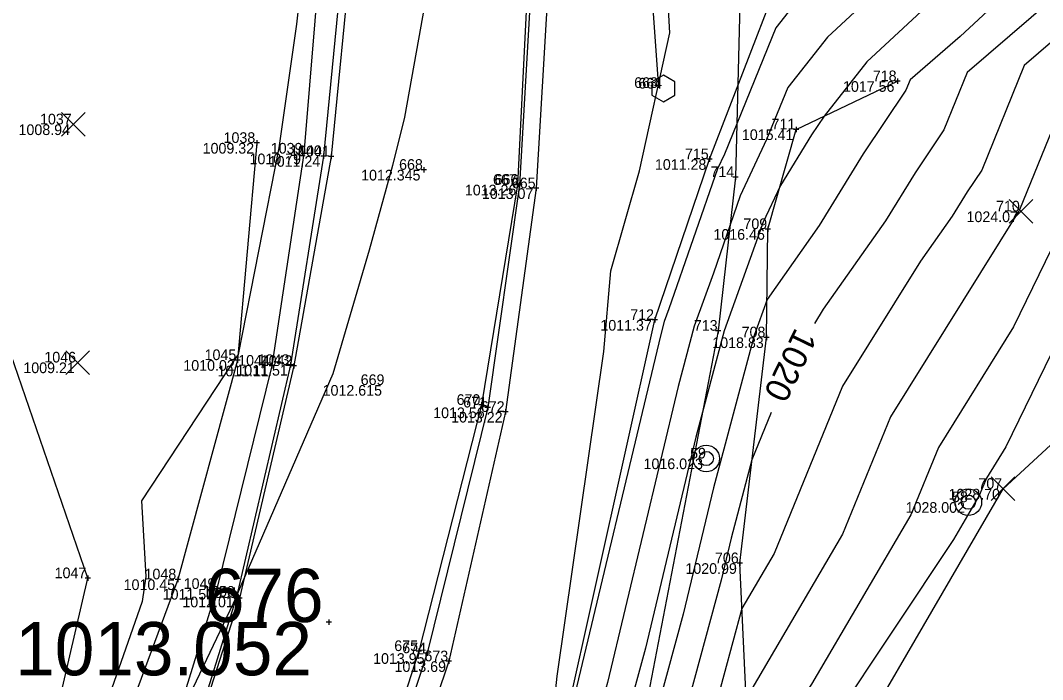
# Model space of a CAD drawing. Extents: x 2354693 to 2355622, y 637071 to 710080.
# Drawn here: x 2355315.1 to 2355430.4, y 709108.7 to 709182.9 of the extents above; entities that cross this region are included whole.
import ezdxf

# ---------------------------------------------------------------- set-up
doc = ezdxf.new("R2010")
doc.units = 0
for name, color, linetype in [('Default', 7, 'Continuous'), ('DT_X_Contour_Major', 7, 'Continuous'), ('DT_X_Contour_Minor', 7, 'Continuous'), ('PM_X_Surveyed_Line', 7, 'Continuous'), ('PV_X_EOP', 7, 'Continuous'), ('PV_X_Shoulder', 7, 'Continuous'), ('RD_X_Cells', 7, 'Continuous'), ('RD_X_GR_Lt', 7, 'Continuous'), ('SV_X_Mon_Cells_Found', 7, 'Continuous'), ('SV_X_Random_Point', 7, 'Continuous'), ('SV_X_Shot_Marker', 7, 'Continuous'), ('SV_X_Text_Elevation', 7, 'Continuous'), ('SV_X_Text_Name', 7, 'Continuous'), ('SV_X_Toe_of_Slope', 7, 'Continuous'), ('SV_X_Top_of_Bank', 7, 'Continuous'), ('VG_X_Tree_Line_Rt', 7, 'Continuous')]:
    doc.layers.add(name, color=color, linetype=linetype)

msp = doc.modelspace()

# ---------------------------------------------------------------- linework, layer by layer
at = {"layer": 'Default'}
msp.add_lwpolyline([(2355263.76, 708986.4), (2355330.91, 709003.61), (2355347.35, 709002.09), (2355387.45, 709051.54), (2355402.1, 709089.16), (2355425.96, 709130.16), (2355495.56, 709194.41), (2355530.33, 709221.46), (2355525, 709302.12), (2355509.66, 709318.33), (2355534.8, 709413.26), (2355566.11, 709428.47), (2355585.74, 709473.78), (2355589.64, 709532.44), (2355608.23, 709591.27)], dxfattribs=at)
msp.add_lwpolyline([(2355263.76, 708986.4), (2355330.91, 709003.61), (2355347.35, 709002.09), (2355387.45, 709051.54), (2355402.1, 709089.16), (2355425.96, 709130.16), (2355495.56, 709194.41), (2355530.33, 709221.46), (2355525, 709302.12), (2355509.66, 709318.33), (2355534.8, 709413.26), (2355566.11, 709428.47), (2355585.74, 709473.78), (2355589.64, 709532.44), (2355608.23, 709591.27)], dxfattribs=at)
at = {"layer": 'DT_X_Contour_Major'}
for points in [[(2355456.69, 709227.11), (2355457.48, 709226.2), (2355459.26, 709225.12), (2355454.22, 709205.33), (2355454.08, 709205.14), (2355453.9, 709204.8), (2355453.96, 709204.72), (2355452.92, 709203.76), (2355421.91, 709177.07), (2355419.27, 709170.6), (2355416.05, 709165.77), (2355412.7, 709160.36), (2355405.68, 709150.4), (2355404.68, 709148.79)], [(2355456.69, 709227.11), (2355457.48, 709226.2), (2355459.26, 709225.12), (2355454.22, 709205.33), (2355454.08, 709205.14), (2355453.9, 709204.8), (2355453.96, 709204.72), (2355452.92, 709203.76), (2355421.91, 709177.07), (2355419.27, 709170.6), (2355416.05, 709165.77), (2355412.7, 709160.36), (2355405.68, 709150.4), (2355404.68, 709148.79)], [(2355347.04, 709193.49), (2355347.17, 709190.66), (2355346.28, 709182.54), (2355344.27, 709168.58), (2355339.69, 709145.3), (2355339.23, 709144.66), (2355328.8, 709128.82), (2355329.27, 709120.28), (2355328.85, 709117.46), (2355322.25, 709098.57)], [(2355347.04, 709193.49), (2355347.17, 709190.66), (2355346.28, 709182.54), (2355344.27, 709168.58), (2355339.69, 709145.3), (2355339.23, 709144.66), (2355328.8, 709128.82), (2355329.27, 709120.28), (2355328.85, 709117.46), (2355322.25, 709098.57)], [(2355399.81, 709138.75), (2355397.63, 709133.42), (2355395.27, 709124.59), (2355394.15, 709119.88), (2355389.34, 709102.14), (2355388.09, 709097.39), (2355383.82, 709092.9), (2355374.92, 709068.12), (2355369.01, 709054.1), (2355364.95, 709045.81)], [(2355399.81, 709138.75), (2355397.63, 709133.42), (2355395.27, 709124.59), (2355394.15, 709119.88), (2355389.34, 709102.14), (2355388.09, 709097.39), (2355383.82, 709092.9), (2355374.92, 709068.12), (2355369.01, 709054.1), (2355364.95, 709045.81)]]:
    msp.add_lwpolyline(points, dxfattribs=at)
at = {"layer": 'DT_X_Contour_Minor'}
for points in [[(2355432.86, 709227.06), (2355429.2, 709222.75), (2355423.82, 709215.5), (2355413.6, 709196.23), (2355417.38, 709191.51), (2355406.15, 709181.07), (2355401.67, 709175.4), (2355399.28, 709169.52), (2355396.31, 709163.17), (2355393.28, 709154.48), (2355391.12, 709148.5), (2355389.3, 709141.69), (2355381.34, 709108.35), (2355380.04, 709103.59), (2355379.71, 709102.31), (2355378.56, 709101.1), (2355376.17, 709094.45), (2355359.35, 709054.56), (2355355.96, 709047.61), (2355331.07, 709003.59)], [(2355432.86, 709227.06), (2355429.2, 709222.75), (2355423.82, 709215.5), (2355413.6, 709196.23), (2355417.38, 709191.51), (2355406.15, 709181.07), (2355401.67, 709175.4), (2355399.28, 709169.52), (2355396.31, 709163.17), (2355393.28, 709154.48), (2355391.12, 709148.5), (2355389.3, 709141.69), (2355381.34, 709108.35), (2355380.04, 709103.59), (2355379.71, 709102.31), (2355378.56, 709101.1), (2355376.17, 709094.45), (2355359.35, 709054.56), (2355355.96, 709047.61), (2355331.07, 709003.59)], [(2355433.91, 709212.05), (2355427.03, 709199.09), (2355429.57, 709195.91), (2355410.59, 709178.28), (2355405.76, 709172.16), (2355404.34, 709170.04), (2355400.84, 709164.36), (2355398.86, 709160.13), (2355398.29, 709158.51), (2355394.5, 709147.97), (2355391.29, 709135.99), (2355385.61, 709112.19), (2355383.14, 709103.1), (2355382.5, 709100.67), (2355380.31, 709098.37), (2355375.75, 709085.67), (2355362.57, 709054.41), (2355353.88, 709036.62), (2355335, 709003.23)], [(2355433.91, 709212.05), (2355427.03, 709199.09), (2355429.57, 709195.91), (2355410.59, 709178.28), (2355405.76, 709172.16), (2355404.34, 709170.04), (2355400.84, 709164.36), (2355398.86, 709160.13), (2355398.29, 709158.51), (2355394.5, 709147.97), (2355391.29, 709135.99), (2355385.61, 709112.19), (2355383.14, 709103.1), (2355382.5, 709100.67), (2355380.31, 709098.37), (2355375.75, 709085.67), (2355362.57, 709054.41), (2355353.88, 709036.62), (2355335, 709003.23)], [(2355455.82, 709201.52), (2355428.34, 709177.87), (2355423.54, 709166.09), (2355421.9, 709163.64), (2355420.2, 709160.88), (2355416.62, 709155.81), (2355407.85, 709141.74), (2355400.15, 709122.88), (2355396.5, 709116.66), (2355392.43, 709101.65), (2355390.88, 709095.75), (2355385.57, 709090.16), (2355374.5, 709059.34), (2355372.23, 709053.95), (2355347.65, 709003.65), (2355346.79, 709002.14)], [(2355455.82, 709201.52), (2355428.34, 709177.87), (2355423.54, 709166.09), (2355421.9, 709163.64), (2355420.2, 709160.88), (2355416.62, 709155.81), (2355407.85, 709141.74), (2355400.15, 709122.88), (2355396.5, 709116.66), (2355392.43, 709101.65), (2355390.88, 709095.75), (2355385.57, 709090.16), (2355374.5, 709059.34), (2355372.23, 709053.95), (2355347.65, 709003.65), (2355346.79, 709002.14)], [(2355401.7, 709183.87), (2355400.31, 709182.11), (2355394.55, 709167.89), (2355393.76, 709166.21), (2355388.26, 709150.46), (2355387.74, 709149.02), (2355387.31, 709147.39), (2355377.07, 709104.51), (2355376.95, 709104.07), (2355376.92, 709103.95), (2355376.81, 709103.84), (2355376.59, 709103.23), (2355372.38, 709093.25), (2355374.65, 709102.38), (2355375.23, 709104.82), (2355375.66, 709109.07), (2355380.92, 709145.65), (2355381.7, 709154.71), (2355384.94, 709165.98), (2355388.38, 709181.55), (2355387.25, 709201.61)], [(2355401.7, 709183.87), (2355400.31, 709182.11), (2355394.55, 709167.89), (2355393.76, 709166.21), (2355388.26, 709150.46), (2355387.74, 709149.02), (2355387.31, 709147.39), (2355377.07, 709104.51), (2355376.95, 709104.07), (2355376.92, 709103.95), (2355376.81, 709103.84), (2355376.59, 709103.23), (2355372.38, 709093.25), (2355374.65, 709102.38), (2355375.23, 709104.82), (2355375.66, 709109.07), (2355380.92, 709145.65), (2355381.7, 709154.71), (2355384.94, 709165.98), (2355388.38, 709181.55), (2355387.25, 709201.61)], [(2355441.77, 709200.32), (2355421.1, 709181.12), (2355415.48, 709176.27), (2355415, 709175.1), (2355410.19, 709167.9), (2355405.21, 709159.83), (2355399.33, 709151.49), (2355397.87, 709147.45), (2355393.28, 709130.29), (2355389.88, 709116.04), (2355386.24, 709102.62), (2355385.3, 709099.03), (2355382.07, 709095.63), (2355375.33, 709076.89), (2355365.79, 709054.26), (2355351.8, 709025.63), (2355338.93, 709002.87)], [(2355441.77, 709200.32), (2355421.1, 709181.12), (2355415.48, 709176.27), (2355415, 709175.1), (2355410.19, 709167.9), (2355405.21, 709159.83), (2355399.33, 709151.49), (2355397.87, 709147.45), (2355393.28, 709130.29), (2355389.88, 709116.04), (2355386.24, 709102.62), (2355385.3, 709099.03), (2355382.07, 709095.63), (2355375.33, 709076.89), (2355365.79, 709054.26), (2355351.8, 709025.63), (2355338.93, 709002.87)], [(2355362.05, 709192.16), (2355358.45, 709172.04), (2355357.11, 709166.59), (2355354.46, 709157.07), (2355350.37, 709143.12), (2355339.59, 709118.3), (2355339.54, 709118.17), (2355339.49, 709118.02), (2355332.34, 709102.98), (2355330.16, 709098.09), (2355328.96, 709094.77), (2355325.41, 709087), (2355319.12, 709073.27), (2355312.74, 709068.84), (2355306.43, 709059.31), (2355290.09, 709038.24), (2355286.78, 709031.66), (2355285.96, 709030.24), (2355285.39, 709028.91), (2355262.53, 708987.18)], [(2355362.05, 709192.16), (2355358.45, 709172.04), (2355357.11, 709166.59), (2355354.46, 709157.07), (2355350.37, 709143.12), (2355339.59, 709118.3), (2355339.54, 709118.17), (2355339.49, 709118.02), (2355332.34, 709102.98), (2355330.16, 709098.09), (2355328.96, 709094.77), (2355325.41, 709087), (2355319.12, 709073.27), (2355312.74, 709068.84), (2355306.43, 709059.31), (2355290.09, 709038.24), (2355286.78, 709031.66), (2355285.96, 709030.24), (2355285.39, 709028.91), (2355262.53, 708987.18)], [(2355434.77, 709178.67), (2355427.81, 709161.59), (2355427.75, 709161.5), (2355427.69, 709161.4), (2355427.56, 709161.22), (2355413.25, 709138.29), (2355407.86, 709125.05), (2355396.98, 709106.54), (2355395.53, 709101.17), (2355393.68, 709094.11), (2355387.32, 709087.42), (2355375.84, 709055.46), (2355374.95, 709053.73), (2355351.99, 709007.81)], [(2355434.77, 709178.67), (2355427.81, 709161.59), (2355427.75, 709161.5), (2355427.69, 709161.4), (2355427.56, 709161.22), (2355413.25, 709138.29), (2355407.86, 709125.05), (2355396.98, 709106.54), (2355395.53, 709101.17), (2355393.68, 709094.11), (2355387.32, 709087.42), (2355375.84, 709055.46), (2355374.95, 709053.73), (2355351.99, 709007.81)], [(2355443.81, 709170.88), (2355426.26, 709134.89), (2355424.07, 709131.37), (2355423.26, 709129.4), (2355420.36, 709124.46), (2355400.1, 709094.01), (2355399.26, 709090.83), (2355390.83, 709081.95), (2355384.38, 709064), (2355378.76, 709053.06), (2355362.8, 709021.14)], [(2355443.81, 709170.88), (2355426.26, 709134.89), (2355424.07, 709131.37), (2355423.26, 709129.4), (2355420.36, 709124.46), (2355400.1, 709094.01), (2355399.26, 709090.83), (2355390.83, 709081.95), (2355384.38, 709064), (2355378.76, 709053.06), (2355362.8, 709021.14)], [(2355435.74, 709166.06), (2355427.13, 709148.41), (2355418.66, 709134.83), (2355415.56, 709127.23), (2355404.35, 709108.14), (2355398.13, 709098.79), (2355396.47, 709092.47), (2355389.07, 709084.69), (2355380.11, 709059.73), (2355376.86, 709053.4), (2355357.39, 709014.47)], [(2355435.74, 709166.06), (2355427.13, 709148.41), (2355418.66, 709134.83), (2355415.56, 709127.23), (2355404.35, 709108.14), (2355398.13, 709098.79), (2355396.47, 709092.47), (2355389.07, 709084.69), (2355380.11, 709059.73), (2355376.86, 709053.4), (2355357.39, 709014.47)]]:
    msp.add_lwpolyline(points, dxfattribs=at)
at = {"layer": 'PM_X_Surveyed_Line'}
for points in [[(2355180.15, 709561.24), (2355214.75, 709522.89), (2355249.31, 709484.27), (2355284.02, 709443.14), (2355315.55, 709399.77), (2355328.89, 709377.57), (2355342.97, 709349.79), (2355353.37, 709324.19), (2355361.35, 709299.65), (2355367.76, 709272.47), (2355372.19, 709243.49), (2355373.87, 709217.88), (2355371.21, 709164.41), (2355367.13, 709139.62), (2355360.06, 709111.88), (2355351.62, 709085.78), (2355342.5, 709062.34), (2355329.45, 709031.42), (2355320.62, 709012.58)], [(2355165.86, 709547.27), (2355199.55, 709510.04), (2355233.99, 709470.59), (2355267.54, 709430.37), (2355282.6, 709410.56), (2355297.68, 709388.57), (2355309.4, 709369.45), (2355323.83, 709342.43), (2355334.06, 709318.38), (2355342.29, 709293.43), (2355348.47, 709267.17), (2355351.87, 709240.38), (2355352.96, 709217.38), (2355352.46, 709191.09), (2355350.19, 709167.62), (2355345.96, 709144.01), (2355339.85, 709117.86), (2355332.1, 709093.74), (2355322.6, 709069.08), (2355314.61, 709050.66), (2355300.36, 709021.7)]]:
    msp.add_lwpolyline(points, dxfattribs=at)
at = {"layer": 'PV_X_EOP'}
for points in [[(2355180.81, 709561.74), (2355215.64, 709523.56), (2355249.92, 709484.36), (2355284.41, 709443.36), (2355315.94, 709399.97), (2355329.75, 709378.36), (2355343.52, 709350.1), (2355349.22, 709351.4), (2355359.3, 709326.8), (2355367.59, 709301.75), (2355374.11, 709275.91), (2355368.17, 709272.69), (2355372.5, 709243.56), (2355374.5, 709217.66), (2355371.41, 709164.43), (2355367.84, 709139.33), (2355361.02, 709111.64), (2355352.39, 709085.56), (2355343.44, 709061.97), (2355330.49, 709031.08), (2355321.14, 709011.8)], [(2355165.32, 709546.95), (2355198.99, 709509.5), (2355233.4, 709470.11), (2355266.73, 709429.76), (2355281.93, 709410.08), (2355297.05, 709388.17), (2355308.64, 709369.04), (2355321.45, 709342.93), (2355321.34, 709342.62), (2355331.82, 709317.68), (2355340.04, 709292.97), (2355346.6, 709266.72), (2355349.96, 709239.9), (2355351.76, 709217.38), (2355351.56, 709190.76), (2355349.32, 709167.66), (2355345.61, 709144.12), (2355339.52, 709118.01), (2355331.95, 709093.67), (2355322.31, 709069.24), (2355314.27, 709051.11), (2355300.29, 709022.25)]]:
    msp.add_lwpolyline(points, dxfattribs=at)
at = {"layer": 'PV_X_Shoulder'}
for points in [[(2355370.56, 709271.65), (2355375.13, 709244.15), (2355376.46, 709217.44), (2355373.31, 709164.03), (2355369.83, 709138.83), (2355363.46, 709110.73), (2355354.73, 709084.84), (2355345.67, 709061.24), (2355332.68, 709029.85), (2355323.4, 709011.31)], [(2355350.69, 709226.18), (2355349.24, 709225.72), (2355348.98, 709190.63), (2355347.11, 709167.94), (2355343.48, 709144.04), (2355337.29, 709118.88), (2355329.72, 709094.53), (2355320.78, 709071.24), (2355312.54, 709052.23), (2355299, 709024.07)]]:
    msp.add_lwpolyline(points, dxfattribs=at)
at = {"layer": 'RD_X_Cells'}
msp.add_lwpolyline([(2355386.34, 709174.52), (2355387.64, 709173.77), (2355388.94, 709174.52), (2355388.94, 709176.02), (2355387.64, 709176.77), (2355386.34, 709176.02), (2355386.34, 709174.52)], dxfattribs=at)
at = {"layer": 'RD_X_GR_Lt'}
msp.add_lwpolyline([(2355373.99, 709277.32), (2355381.03, 709242.7), (2355383.59, 709226.42), (2355385.2, 709201.58), (2355387.11, 709175.34)], dxfattribs=at)
at = {"layer": 'SV_X_Mon_Cells_Found'}
for centre, radius in [((2355392.48, 709133.58), 1.5), ((2355392.48, 709133.58), 0.8), ((2355422.03, 709128.66), 1.5), ((2355422.03, 709128.66), 0.8)]:
    msp.add_circle(centre, radius, dxfattribs=at)
at = {"layer": 'SV_X_Random_Point'}
for p, q in [((2355319.77, 709169.89), (2355322.43, 709172.56)), ((2355319.77, 709172.56), (2355322.43, 709169.89)), ((2355426.63, 709160.09), (2355429.3, 709162.76)), ((2355426.63, 709162.76), (2355429.3, 709160.09)), ((2355320.26, 709143.06), (2355322.93, 709145.73)), ((2355320.26, 709145.73), (2355322.93, 709143.06)), ((2355424.62, 709128.83), (2355427.29, 709131.5)), ((2355424.62, 709131.5), (2355427.29, 709128.83))]:
    msp.add_line(p, q, dxfattribs=at)
at = {"layer": 'SV_X_Shot_Marker'}
for p, q in [((2355414.35, 709176.1), (2355413.75, 709176.1)), ((2355414.05, 709176.4), (2355414.05, 709175.8)), ((2355402.62, 709170.97), (2355402.62, 709170.37)), ((2355402.92, 709170.67), (2355402.32, 709170.67)), ((2355342.11, 709169.14), (2355341.51, 709169.14)), ((2355341.81, 709169.44), (2355341.81, 709168.84)), ((2355347.41, 709167.94), (2355346.81, 709167.94)), ((2355347.11, 709168.24), (2355347.11, 709167.64)), ((2355349.62, 709167.66), (2355349.02, 709167.66)), ((2355349.32, 709167.96), (2355349.32, 709167.36)), ((2355350.49, 709167.62), (2355349.89, 709167.62)), ((2355350.19, 709167.92), (2355350.19, 709167.32)), ((2355392.84, 709167.61), (2355392.84, 709167.01)), ((2355360.63, 709166.41), (2355360.63, 709165.81)), ((2355393.14, 709167.31), (2355392.54, 709167.31)), ((2355360.93, 709166.11), (2355360.33, 709166.11)), ((2355396.06, 709165.3), (2355395.46, 709165.3)), ((2355395.76, 709165.6), (2355395.76, 709165)), ((2355371.51, 709164.41), (2355370.91, 709164.41)), ((2355371.71, 709164.43), (2355371.11, 709164.43)), ((2355371.21, 709164.71), (2355371.21, 709164.11)), ((2355371.41, 709164.73), (2355371.41, 709164.13)), ((2355373.61, 709164.03), (2355373.01, 709164.03)), ((2355373.31, 709164.33), (2355373.31, 709163.73)), ((2355399.74, 709159.43), (2355399.14, 709159.43)), ((2355399.44, 709159.73), (2355399.44, 709159.13)), ((2355386.98, 709149.19), (2355386.38, 709149.19)), ((2355386.68, 709149.49), (2355386.68, 709148.89)), ((2355394.13, 709147.98), (2355393.53, 709147.98)), ((2355393.83, 709148.28), (2355393.83, 709147.68)), ((2355399.57, 709147.23), (2355398.97, 709147.23)), ((2355399.27, 709147.53), (2355399.27, 709146.93)), ((2355339.93, 709144.67), (2355339.33, 709144.67)), ((2355339.63, 709144.97), (2355339.63, 709144.37)), ((2355343.48, 709144.34), (2355343.48, 709143.74)), ((2355345.61, 709144.42), (2355345.61, 709143.82)), ((2355343.78, 709144.04), (2355343.18, 709144.04)), ((2355345.91, 709144.12), (2355345.31, 709144.12)), ((2355346.26, 709144.01), (2355345.66, 709144.01)), ((2355345.96, 709144.31), (2355345.96, 709143.71)), ((2355367.13, 709139.93), (2355367.13, 709139.32)), ((2355367.43, 709139.62), (2355366.83, 709139.62)), ((2355368.14, 709139.33), (2355367.54, 709139.33)), ((2355367.84, 709139.63), (2355367.84, 709139.03)), ((2355370.13, 709138.83), (2355369.53, 709138.83)), ((2355369.83, 709139.13), (2355369.83, 709138.53)), ((2355396.56, 709121.78), (2355395.96, 709121.78)), ((2355396.26, 709122.08), (2355396.26, 709121.48)), ((2355322.75, 709120.39), (2355322.75, 709119.79)), ((2355332.89, 709120.26), (2355332.89, 709119.66)), ((2355323.05, 709120.09), (2355322.45, 709120.09)), ((2355333.19, 709119.96), (2355332.59, 709119.96)), ((2355337.29, 709119.18), (2355337.29, 709118.58)), ((2355337.59, 709118.88), (2355336.99, 709118.88)), ((2355339.82, 709118.01), (2355339.22, 709118.01)), ((2355339.52, 709118.31), (2355339.52, 709117.71)), ((2355340.15, 709117.86), (2355339.55, 709117.86)), ((2355339.85, 709118.16), (2355339.85, 709117.56)), ((2355350.23, 709115.15), (2355349.63, 709115.15)), ((2355349.93, 709115.45), (2355349.93, 709114.85)), ((2355360.06, 709112.18), (2355360.06, 709111.58)), ((2355360.36, 709111.88), (2355359.76, 709111.88)), ((2355361.32, 709111.64), (2355360.72, 709111.64)), ((2355361.02, 709111.94), (2355361.02, 709111.34)), ((2355363.46, 709111.03), (2355363.46, 709110.43)), ((2355363.76, 709110.73), (2355363.16, 709110.73))]:
    msp.add_line(p, q, dxfattribs=at)
at = {"layer": 'SV_X_Toe_of_Slope'}
for points in [[(2355330.91, 709003.61), (2355357.29, 709054.66), (2355376.63, 709104.12), (2355386.68, 709149.19), (2355392.84, 709167.31), (2355399.71, 709185.13), (2355454.61, 709204.96), (2355491.09, 709216.85), (2355522.63, 709235.09)], [(2355341.81, 709169.14), (2355339.63, 709144.67), (2355332.89, 709119.96), (2355324.12, 709096.3), (2355318.2, 709074.39)]]:
    msp.add_lwpolyline(points, dxfattribs=at)
at = {"layer": 'SV_X_Top_of_Bank'}
msp.add_lwpolyline([(2355387.45, 709051.54), (2355395.31, 709074.94), (2355402.1, 709089.16), (2355397.25, 709100.9), (2355396.26, 709121.78), (2355399.27, 709147.23), (2355399.44, 709159.43), (2355402.62, 709170.67), (2355414.05, 709176.1)], dxfattribs=at)
at = {"layer": 'VG_X_Tree_Line_Rt'}
for points in [[(2355286.87, 709031.33), (2355312.43, 709075.83), (2355322.75, 709120.09), (2355304.91, 709171.78), (2355297.85, 709210.36), (2355206.48, 709334.22), (2355207.86, 709373.6), (2355249.36, 709399.77), (2355239.7, 709433.16), (2355219.43, 709459.42), (2355185.29, 709497.16), (2355152.29, 709534.91)], [(2355430.11, 709344.44), (2355398.4, 709251.33), (2355397.95, 709252.38), (2355395.76, 709165.3), (2355393.83, 709147.98), (2355384.97, 709102.06), (2355364.4, 709052.05), (2355337.3, 709001.3)]]:
    msp.add_lwpolyline(points, dxfattribs=at)

# ---------------------------------------------------------------- texts
at = {"layer": 'DT_X_Contour_Major'}
msp.add_text('1020', height=2.8, rotation=244.1244, dxfattribs=at).set_placement((2355402.54, 709148.42))
msp.add_text('1020', height=2.8, rotation=244.1244, dxfattribs=at).set_placement((2355402.54, 709148.42))
at = {"layer": 'SV_X_Text_Elevation'}
for s, height, p in [('1017.56', 1.2, (2355407.9, 709174.9)), ('1008.94', 1.2, (2355314.93, 709170.03)), ('1015.41', 1.2, (2355396.5, 709169.47)), ('1009.32', 1.2, (2355335.69, 709167.94)), ('1010.79', 1.2, (2355340.98, 709166.74)), ('1011.24', 1.2, (2355343.15, 709166.46)), ('1011.28', 1.2, (2355386.69, 709166.11)), ('1012.345', 1.2, (2355353.56, 709164.91)), ('1013.26', 1.2, (2355365.26, 709163.23)), ('1013.07', 1.2, (2355367.18, 709162.83)), ('1024.07', 1.2, (2355421.83, 709160.22)), ('1016.46', 1.2, (2355393.29, 709158.23)), ('1011.37', 1.2, (2355380.54, 709147.99)), ('1018.83', 1.2, (2355393.16, 709146.03)), ('1009.21', 1.2, (2355315.47, 709143.2)), ('1010.02', 1.2, (2355333.51, 709143.47)), ('1011.11', 1.2, (2355337.36, 709142.84)), ('1011.51', 1.2, (2355339.49, 709142.92)), ('1012.615', 1.2, (2355349.22, 709140.66)), ('1013.56', 1.2, (2355361.69, 709138.13)), ('1013.22', 1.2, (2355363.71, 709137.63)), ('1016.023', 1.2, (2355385.41, 709132.38)), ('1028.70', 1.2, (2355419.8, 709128.96)), ('1028.002', 1.2, (2355414.96, 709127.46)), ('1020.99', 1.2, (2355390.13, 709120.58)), ('1010.45', 1.2, (2355326.78, 709118.76)), ('1011.53', 1.2, (2355331.18, 709117.68)), ('1012.01', 1.2, (2355333.4, 709116.81)), ('1013.052', 6, (2355314.55, 709109.15)), ('1013.95', 1.2, (2355354.91, 709110.44)), ('1013.69', 1.2, (2355357.33, 709109.53))]:
    msp.add_text(s, height=height, dxfattribs=at).set_placement(p)
at = {"layer": 'SV_X_Text_Name'}
for s, height, p in [('718', 1.2, (2355411.26, 709176.1)), ('663', 1.2, (2355384.35, 709175.34)), ('664', 1.2, (2355384.82, 709175.27)), ('1037', 1.2, (2355317.35, 709171.23)), ('711', 1.2, (2355399.85, 709170.67)), ('1038', 1.2, (2355338.05, 709169.14)), ('1039', 1.2, (2355343.37, 709167.94)), ('1040', 1.2, (2355345.55, 709167.66)), ('1041', 1.2, (2355346.46, 709167.62)), ('715', 1.2, (2355390.08, 709167.31)), ('668', 1.2, (2355357.84, 709166.11)), ('714', 1.2, (2355392.95, 709165.3)), ('667', 1.2, (2355368.43, 709164.41)), ('666', 1.2, (2355368.61, 709164.43)), ('665', 1.2, (2355370.55, 709164.03)), ('710', 1.2, (2355425.16, 709161.42)), ('709', 1.2, (2355396.67, 709159.43)), ('712', 1.2, (2355383.91, 709149.19)), ('713', 1.2, (2355391.08, 709147.98)), ('708', 1.2, (2355396.47, 709147.23)), ('1046', 1.2, (2355317.84, 709144.4)), ('1045', 1.2, (2355335.91, 709144.67)), ('1044', 1.2, (2355339.7, 709144.04)), ('1043', 1.2, (2355341.9, 709144.12)), ('1042', 1.2, (2355342.24, 709144.01)), ('669', 1.2, (2355353.51, 709141.86)), ('670', 1.2, (2355364.33, 709139.62)), ('671', 1.2, (2355365.07, 709139.33)), ('672', 1.2, (2355367.06, 709138.83)), ('59', 1.2, (2355390.66, 709133.58)), ('707', 1.2, (2355423.17, 709130.16)), ('58', 1.2, (2355420.19, 709128.66)), ('706', 1.2, (2355393.46, 709121.78)), ('1047', 1.2, (2355319, 709120.09)), ('1048', 1.2, (2355329.14, 709119.96)), ('676', 6, (2355335.94, 709115.15)), ('1049', 1.2, (2355333.55, 709118.88)), ('1050', 1.2, (2355335.75, 709118.01)), ('1051', 1.2, (2355336.12, 709117.86)), ('675', 1.2, (2355357.3, 709111.88)), ('674', 1.2, (2355358.2, 709111.64)), ('673', 1.2, (2355360.7, 709110.73))]:
    msp.add_text(s, height=height, dxfattribs=at).set_placement(p)

doc.saveas('drawing.dxf')
